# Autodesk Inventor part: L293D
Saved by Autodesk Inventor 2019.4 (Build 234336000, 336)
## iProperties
Created: 2020-03
Part Number: L293D
Material: Generic
Document SubType Name: Modeling
Designer: Administrator
Density: 1 g/cm^3
Appearance: Default
Title: DIL16
Author: Administrator
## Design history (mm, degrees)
feature "DIL16"
body "Solid1"
